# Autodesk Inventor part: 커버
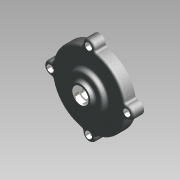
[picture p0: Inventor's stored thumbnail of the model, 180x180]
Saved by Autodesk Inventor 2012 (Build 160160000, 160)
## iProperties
Created: 2012-05
Part Number: 커버
Document SubType Name: 모델링
Designer: SeoGD™
Material: 알루미늄-6061
Mass: 196.659 g
Surface Area: 278.607 cm^2
Volume: 72.5678 cm^3
Density: 2.71 g/cm^3
변환 표준: STEP AP214IS
파일 이름: C:\Users\SeoGD\Desktop\?쒗뿕\而ㅻ쾭-1.stp
전처리기: Build: 253, Release: 2010 SP1 - Date: Wed 07/29/2009
전송 단위: 밀리미터
불확실성: 0.01
Author: SeoGD™
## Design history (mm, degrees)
sketch "스케치1"
  geometry: L1 (0, 0)-(0, 26); L2 (50, 0)-(50, 15); L3 (50, 15)-(25, 15); L4 (25, 15)-(25, 21); L5 (25, 21)-(15, 21); L6 (15, 21)-(13.66, 26); L7 (13.66, 26)-(10, 26); L8 (50, 0)-(45, 0); L9 (45, 0)-(45, 10); L10 (45, 10)-(14.5, 10); L11 (14.5, 10)-(13.266, 3); L12 (13.266, 3)-(11, 3); L13 (11, 3)-(11, 16); L14 (11, 16)-(7.5, 16); L15 (7.5, 16)-(7.5, 19); L16 (7.5, 19)-(10, 19); L17 (10, 19)-(10, 26)
  constraints: 34 end point, 10 parallel, 2 perpendicular, 2 point on line, 1 vertical
  dimensions: "d11" = 100 diameter of L2 L1; "d12" = 22 diameter of L13 L1; "d13" = 90 diameter of L9 L1; "d14" = 15 distance between parallel lines of L3 L8; "d15" = 10 distance between parallel lines of L8 L10; "d16" = 29 diameter of L10.end L1; "d17" = 100 deg angle of L11 L10; "d18" = 7 distance between parallel lines of L12 L10; "d19" = 13 distance between parallel lines of L14 L12; "d20" = 3 distance between parallel lines of L16 L14; "d21" = 15 diameter of L15 L1; "d22" = 20 diameter of L17 L1; "d23" = 30 diameter of L5.end L1; "d24" = 6 distance between parallel lines of L5 L3; "d25" = 50 diameter of L4 L1; "d26" = 105 deg angle of L5 L6; "d50" = 26 distance of L1.start L1.end
revolve "회전1" sketch "스케치1" stored, may be unused: angle "d27" = 90 deg
sketch "스케치2" dims "d29" = 104
  geometry: A1 r 8.5 centre (0, 52) between (8.074, 49.344) and (-8.074, 49.344); A2 r 50 centre (0, 0) between (-8.074, 49.344) and (8.074, 49.344) reference; 2 further points
  constraints: 4 point on circle, 2 vertical alignment, 1 centre point, 1 coincident, 2 other
  dimensions: "d28" = 17 diameter of A1
extrude "돌출1" join sketch "스케치2" stored distance "d30" = 10; taper "d31" = 0 deg
fillet "모깎기3" dims "d32" = 3
fillet "모깎기4" dims "d45" = 3, "d46" = 0.2
chamfer "모따기1" distance "d47" = 1; stored, may be unused: second distance "d48" = 2, angle "d49" = 45 deg
hole "구멍2" diameter "d38" = 5.5; stored, may be unused: countersink angle "d42" = 90 deg, drill point angle "d44" = 118 deg; dims "d36" = 10, "d37" = 10, "d39" = 6, "d40" = 9.5, "d41" = 5.4, "d43" = 8
node "솔리드1"
node "솔리드 본체"
node "곡면 본체"
pattern_circular "원형 패턴1" dims angle "d34" = 360 deg
pattern_circular "원형 패턴2" dims angle "d52" = 360 deg
node "솔리드2"
